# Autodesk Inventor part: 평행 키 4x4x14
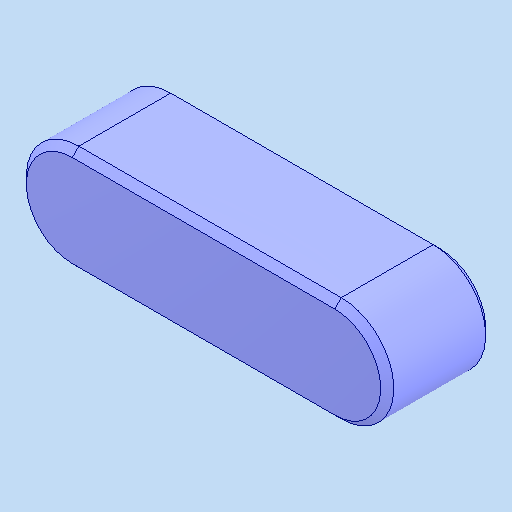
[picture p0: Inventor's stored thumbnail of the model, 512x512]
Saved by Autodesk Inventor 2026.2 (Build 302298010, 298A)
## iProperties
Created: 2026-03
Part Number: 평행 키 4x4x14
Material: 강철, 연강
Description: 키 및 해당 키홈
Document SubType Name: Modeling
Designer: PC-2-03
Density: 7.85 g/cm^3
Appearance: 기본값
Author: jhkim
Sending System: Autodesk Inventor 2026
Preprocessor: ST-DEVELOPER v20.1
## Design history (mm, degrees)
feature "Solid1"
node "솔리드1"
